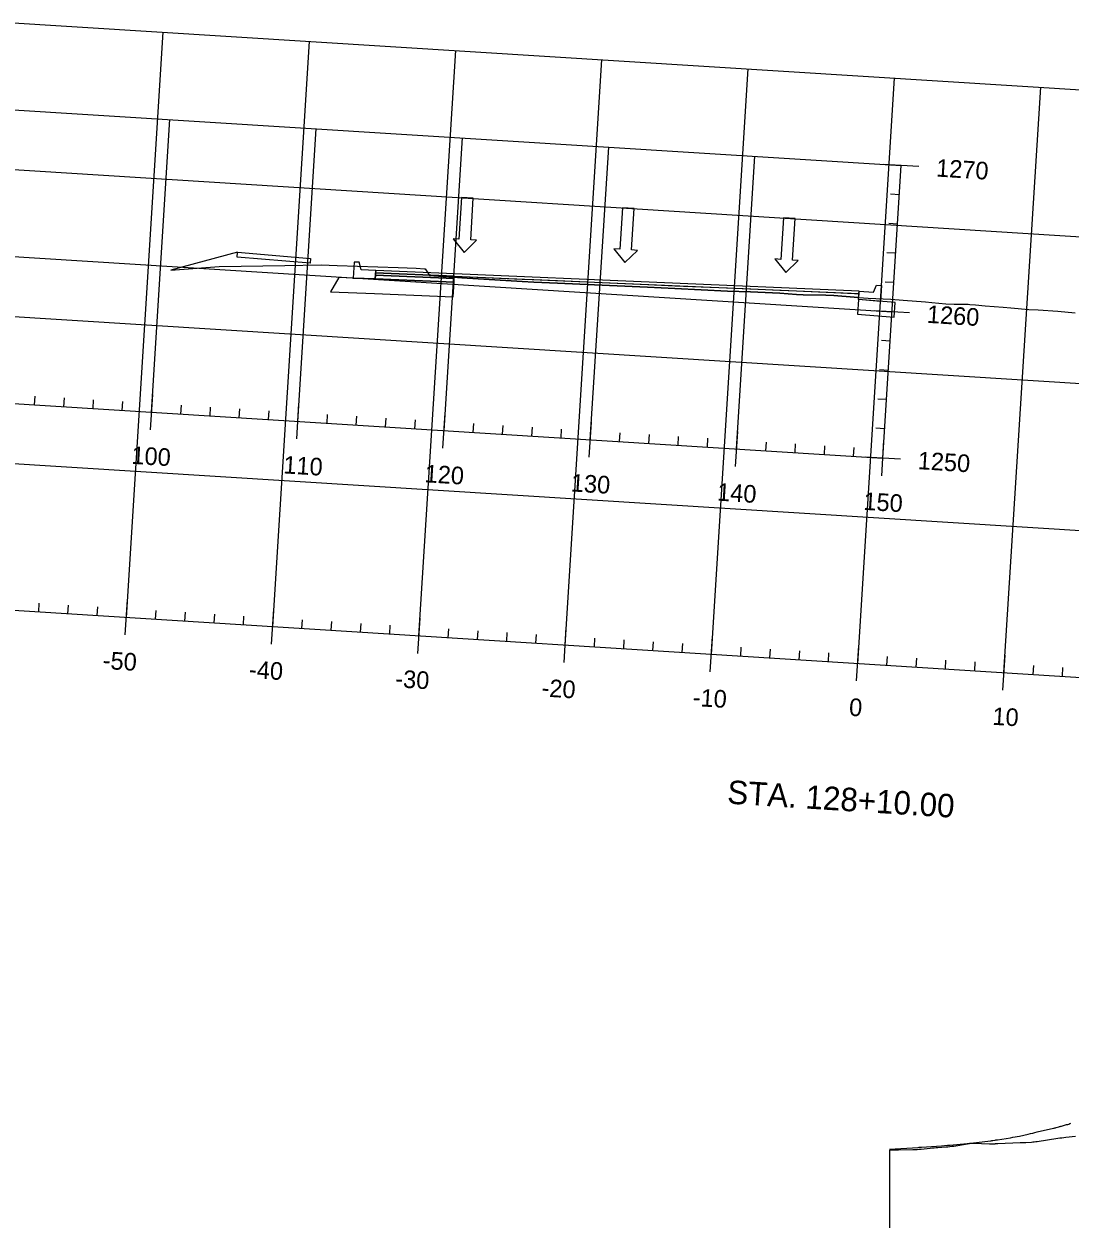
# Model space of a CAD drawing. Extents: x 658976 to 668726, y 639543 to 647196.
# Drawn here: x 660866.2 to 661223.2, y 641758.1 to 642165.7 of the extents above; entities that cross this region are included whole.
import ezdxf

# ---------------------------------------------------------------- set-up
doc = ezdxf.new("R2010")
doc.units = 0
for name, color, linetype in [('Ex_Major Contours', 7, 'Continuous'), ('R_Axis', 7, 'Continuous'), ('R_Axis Annot', 7, 'Continuous'), ('R_Exist Surface', 7, 'Continuous'), ('R_Fin Surface', 7, 'Continuous'), ('R_Grid', 7, 'Continuous'), ('R_MOT', 7, 'Continuous'), ('R_Proposed Const Limits', 7, 'Continuous'), ('R_Proposed Road', 7, 'Continuous'), ('R_Sub Surface', 7, 'Continuous')]:
    doc.layers.add(name, color=color, linetype=linetype)

msp = doc.modelspace()

# ---------------------------------------------------------------- linework, layer by layer
for points in [[(660986.27, 642081.64), (660981.27, 642081.86), (660980.6, 642084.4), (660978.93, 642084.51), (660978.59, 642079.05), (660986.09, 642078.73)], [(661151.15, 642074.59), (661156.14, 642074.18), (661157.12, 642076.62), (661158.79, 642076.52), (661158.45, 642071.06), (661150.97, 642071.68)]]:
    msp.add_lwpolyline(points, close=True)
at = {"layer": 'Ex_Major Contours'}
for points in [[(661161.51, 641781.89), (661171.34, 641782.56), (661171.64, 641782.58), (661172.15, 641782.61), (661172.24, 641782.62), (661172.32, 641782.62), (661172.41, 641782.63), (661172.49, 641782.63), (661179.31, 641783.12), (661180.31, 641783.19), (661181.3, 641783.27), (661182.29, 641783.36), (661183.28, 641783.45), (661189.25, 641784.04), (661189.27, 641784.04), (661189.31, 641784.04), (661196.04, 641784.82), (661196.24, 641784.84), (661196.44, 641784.87), (661196.64, 641784.89), (661196.83, 641784.92), (661197.62, 641785.04), (661197.82, 641785.07), (661198.01, 641785.1), (661198.21, 641785.13), (661198.41, 641785.16), (661202.85, 641785.85), (661203.61, 641785.98), (661204.37, 641786.11), (661205.13, 641786.26), (661205.88, 641786.43), (661208.9, 641787.11), (661209.65, 641787.28), (661210.41, 641787.45), (661211.16, 641787.63), (661211.91, 641787.8), (661217.45, 641789.09), (661217.68, 641789.14), (661217.91, 641789.2), (661218.14, 641789.26), (661218.36, 641789.32), (661219.27, 641789.57), (661219.5, 641789.63), (661219.72, 641789.7), (661219.95, 641789.76), (661220.18, 641789.82), (661221.98, 641790.31), (661222.36, 641790.41), (661222.73, 641790.52), (661223.1, 641790.64), (661223.47, 641790.76)], [(661161.68, 641753.1), (661161.68, 641781.57), (661161.68, 641781.58), (661161.69, 641781.59), (661161.69, 641781.6), (661161.7, 641781.61), (661161.75, 641781.64), (661161.77, 641781.64), (661161.78, 641781.65), (661161.79, 641781.65), (661161.81, 641781.65), (661163.46, 641781.66), (661163.74, 641781.66), (661164.02, 641781.67), (661164.3, 641781.67), (661164.58, 641781.68), (661169.48, 641781.79), (661170.21, 641781.82), (661170.94, 641781.86), (661171.66, 641781.91), (661172.39, 641781.98), (661175.39, 641782.29), (661176.06, 641782.35), (661176.74, 641782.42), (661177.42, 641782.47), (661178.09, 641782.52), (661180.8, 641782.7), (661181.48, 641782.75), (661182.15, 641782.83), (661182.83, 641782.91), (661183.5, 641783.02), (661188.82, 641783.93), (661188.93, 641783.94), (661189.05, 641783.96), (661189.16, 641783.96), (661189.27, 641783.97), (661189.73, 641783.97), (661189.85, 641783.97), (661189.96, 641783.97), (661190.08, 641783.97), (661190.19, 641783.96), (661195.68, 641783.72), (661195.77, 641783.71), (661195.86, 641783.71), (661195.95, 641783.71), (661196.04, 641783.71), (661196.41, 641783.72), (661196.5, 641783.72), (661196.59, 641783.73), (661196.68, 641783.73), (661196.78, 641783.74), (661197.61, 641783.81), (661197.68, 641783.82), (661197.76, 641783.83), (661197.84, 641783.83), (661197.92, 641783.84), (661198.23, 641783.87), (661198.31, 641783.88), (661198.38, 641783.89), (661198.46, 641783.89), (661198.54, 641783.89), (661206.14, 641784.19), (661206.62, 641784.21), (661207.11, 641784.23), (661207.59, 641784.25), (661208.07, 641784.27), (661210, 641784.37), (661210.48, 641784.4), (661210.96, 641784.44), (661211.44, 641784.5), (661211.91, 641784.56), (661218.93, 641785.66), (661219.62, 641785.76), (661220.32, 641785.86), (661221.01, 641785.95), (661221.71, 641786.04), (661225.05, 641786.43)]]:
    msp.add_lwpolyline(points, dxfattribs=at)
at = {"layer": 'R_Axis'}
for p, q in [((661159.27, 642017.62), (661165.54, 642117.43)), ((661171.52, 642117.05), (661159.55, 642117.8)), ((659662.22, 642111.64), (661159.27, 642017.62)), ((661164.91, 642107.45), (661161.91, 642107.63)), ((661164.28, 642097.47), (661161.29, 642097.65)), ((661163.66, 642087.49), (661160.66, 642087.67)), ((661163.03, 642077.51), (661160.03, 642077.69)), ((661168.39, 642067.15), (661156.41, 642067.9)), ((661161.77, 642057.54), (661158.78, 642057.73)), ((661161.15, 642047.56), (661158.15, 642047.75)), ((660869.84, 642035.8), (660870.03, 642038.79)), ((660909.38, 642027.3), (660910.14, 642039.28)), ((660879.82, 642035.17), (660880.01, 642038.17)), ((660889.8, 642034.55), (660889.99, 642037.54)), ((660899.78, 642033.92), (660899.97, 642036.91)), ((660919.74, 642032.67), (660919.93, 642035.66)), ((660929.72, 642032.04), (660929.91, 642035.03)), ((660959.28, 642024.17), (660960.04, 642036.15)), ((661160.52, 642037.58), (661157.53, 642037.77)), ((660939.7, 642031.41), (660939.89, 642034.41)), ((660949.68, 642030.79), (660949.87, 642033.78)), ((660969.64, 642029.53), (660969.83, 642032.53)), ((660979.62, 642028.91), (660979.81, 642031.9)), ((660989.6, 642028.28), (660989.79, 642031.27)), ((660999.58, 642027.65), (660999.77, 642030.65)), ((661009.19, 642021.04), (661009.94, 642033.01)), ((661019.54, 642026.4), (661019.73, 642029.39)), ((661029.52, 642025.77), (661029.71, 642028.77)), ((661039.5, 642025.14), (661039.69, 642028.14)), ((661049.48, 642024.52), (661049.67, 642027.51)), ((661059.09, 642017.9), (661059.84, 642029.88)), ((661108.99, 642014.77), (661109.74, 642026.75)), ((661159.89, 642027.6), (661156.9, 642027.79)), ((661069.44, 642023.26), (661069.63, 642026.26)), ((661079.42, 642022.64), (661079.61, 642025.63)), ((661089.4, 642022.01), (661089.59, 642025)), ((661099.39, 642021.38), (661099.57, 642024.38)), ((661119.35, 642020.13), (661119.53, 642023.12)), ((661129.33, 642019.5), (661129.51, 642022.5)), ((661158.89, 642011.63), (661159.64, 642023.61)), ((661139.31, 642018.88), (661139.49, 642021.87)), ((661149.29, 642018.25), (661149.48, 642021.24)), ((661165.26, 642017.25), (661153.28, 642018)), ((660402.17, 641994.63), (661899.22, 641900.61)), ((660871.24, 641965.17), (660871.43, 641968.16)), ((660881.22, 641964.54), (660881.41, 641967.53)), ((660891.2, 641963.91), (660891.39, 641966.91)), ((660900.81, 641957.3), (660901.56, 641969.28)), ((660911.16, 641962.66), (660911.35, 641965.65)), ((660950.71, 641954.16), (660951.46, 641966.14)), ((660921.15, 641962.03), (660921.33, 641965.03)), ((660931.13, 641961.41), (660931.31, 641964.4)), ((660941.11, 641960.78), (660941.29, 641963.77)), ((660961.07, 641959.53), (660961.25, 641962.52)), ((660971.05, 641958.9), (660971.23, 641961.89)), ((660981.03, 641958.27), (660981.22, 641961.27)), ((661000.61, 641951.03), (661001.36, 641963.01)), ((660991.01, 641957.65), (660991.2, 641960.64)), ((661010.97, 641956.39), (661011.16, 641959.39)), ((661020.95, 641955.77), (661021.14, 641958.76)), ((661030.93, 641955.14), (661031.12, 641958.13)), ((661040.91, 641954.51), (661041.1, 641957.51)), ((661050.51, 641947.9), (661051.27, 641959.87)), ((661060.87, 641953.26), (661061.06, 641956.25)), ((661070.85, 641952.63), (661071.04, 641955.63)), ((661080.83, 641952), (661081.02, 641955)), ((661090.81, 641951.38), (661091, 641954.37)), ((661100.41, 641944.76), (661101.17, 641956.74)), ((661110.77, 641950.12), (661110.96, 641953.12)), ((661150.32, 641941.63), (661151.07, 641953.61)), ((661120.75, 641949.5), (661120.94, 641952.49)), ((661130.73, 641948.87), (661130.92, 641951.86)), ((661140.71, 641948.24), (661140.9, 641951.24)), ((661160.67, 641946.99), (661160.86, 641949.98)), ((661170.65, 641946.36), (661170.84, 641949.36)), ((661200.22, 641938.49), (661200.97, 641950.47)), ((661180.63, 641945.74), (661180.82, 641948.73)), ((661190.61, 641945.11), (661190.8, 641948.1)), ((661210.57, 641943.86), (661210.76, 641946.85)), ((661220.56, 641943.23), (661220.74, 641946.22))]:
    msp.add_line(p, q, dxfattribs=at)
at = {"layer": 'R_Exist Surface'}
msp.add_lwpolyline([(660916.3, 642081.78), (660932.78, 642083.03), (660955.28, 642083.36), (660967.68, 642083.59), (660973.12, 642083.31), (660993.94, 642082.66), (661000.04, 642082.43), (661002.84, 642082.16), (661003.12, 642082.14), (661004.43, 642080.1), (661004.57, 642079.88), (661009.14, 642079.57), (661009.71, 642079.54), (661015.59, 642079.16), (661036.19, 642077.89), (661040.14, 642077.66), (661048.24, 642077.28), (661065.97, 642076.51), (661078.98, 642075.88), (661088.29, 642075.48), (661106.22, 642074.61), (661114.13, 642074.3), (661124.11, 642073.83), (661129.77, 642073.44), (661132.1, 642073.32), (661139.86, 642073.21), (661142.52, 642073.11), (661149.51, 642072.49), (661154.29, 642072.19), (661161.96, 642071.8), (661166.22, 642071.49), (661173.83, 642070.9), (661175.98, 642070.66), (661180.8, 642070.22), (661183.6, 642070.17), (661188.42, 642070.1), (661188.92, 642070.05), (661190.86, 642069.88), (661194.13, 642069.6), (661200.38, 642069.06), (661202.92, 642068.84), (661209.03, 642068.31), (661212.25, 642068.15), (661219.02, 642067.75), (661224.86, 642067.2)], dxfattribs=at)
at = {"layer": 'R_Fin Surface'}
for points in [[(661013.04, 642078.83), (660986.16, 642079.97), (660986.09, 642078.73), (661012.96, 642077.58)], [(661013.09, 642079.66), (660986.22, 642080.81), (660986.16, 642079.97), (661013.04, 642078.83)], [(661013.09, 642079.66), (661015.62, 642079.55), (661036.24, 642078.67), (661040.19, 642078.5), (661048.3, 642078.15), (661066.02, 642077.39), (661079.04, 642076.84), (661088.35, 642076.44), (661106.28, 642075.67), (661114.19, 642075.34), (661124.18, 642074.91), (661129.84, 642074.67), (661132.18, 642074.57), (661139.93, 642074.24), (661142.59, 642074.12), (661149.59, 642073.82), (661151.1, 642073.76), (661151.01, 642072.4), (661149.51, 642072.49), (661142.52, 642073.11), (661139.86, 642073.21), (661132.1, 642073.32), (661129.77, 642073.44), (661124.11, 642073.83), (661114.13, 642074.3), (661106.22, 642074.61), (661088.29, 642075.48), (661078.98, 642075.88), (661065.97, 642076.51), (661048.24, 642077.28), (661040.14, 642077.66), (661036.19, 642077.89), (661015.59, 642079.16), (661013.07, 642079.32)]]:
    msp.add_lwpolyline(points, close=True, dxfattribs=at)
at = {"layer": 'R_Grid'}
for p, q in [((659668.48, 642211.45), (661165.54, 642117.43)), ((660414.7, 642194.23), (661911.75, 642100.21)), ((659665.35, 642161.55), (661162.4, 642067.52)), ((660901.18, 641963.29), (660913.72, 642162.89)), ((660951.09, 641960.15), (660963.62, 642159.76)), ((661000.99, 641957.02), (661013.52, 642156.63)), ((661050.89, 641953.88), (661063.43, 642153.49)), ((661100.79, 641950.75), (661113.33, 642150.36)), ((661150.69, 641947.62), (661163.23, 642147.22)), ((660411.57, 642144.33), (661908.62, 642050.31)), ((661200.59, 641944.48), (661213.13, 642144.09)), ((660909.76, 642033.29), (660916.03, 642133.1)), ((660959.66, 642030.16), (660965.93, 642129.96)), ((661009.56, 642027.03), (661015.83, 642126.83)), ((661059.46, 642023.89), (661065.73, 642123.69)), ((661109.37, 642020.76), (661115.63, 642120.56)), ((661159.27, 642017.62), (661165.54, 642117.43)), ((659662.22, 642111.64), (661159.27, 642017.62)), ((660408.44, 642094.43), (661905.49, 642000.41)), ((660405.3, 642044.53), (661902.35, 641950.51)), ((660402.17, 641994.63), (661899.22, 641900.61))]:
    msp.add_line(p, q, dxfattribs=at)
at = {"layer": 'R_MOT'}
for p, q in [((661015.54, 642106.48), (661014.65, 642092.31)), ((661019.53, 642106.23), (661015.54, 642106.48)), ((661018.64, 642092.06), (661019.53, 642106.23)), ((661070.43, 642103.04), (661069.54, 642088.86)), ((661074.42, 642102.78), (661070.43, 642103.04)), ((661073.53, 642088.61), (661074.42, 642102.78)), ((661125.32, 642099.59), (661124.43, 642085.41)), ((661129.31, 642099.34), (661125.32, 642099.59)), ((661128.42, 642085.16), (661129.31, 642099.34)), ((661014.65, 642092.31), (661012.65, 642092.43)), ((661012.65, 642092.43), (661016.37, 642087.8)), ((661016.37, 642087.8), (661020.63, 642091.93)), ((661020.63, 642091.93), (661018.64, 642092.06)), ((661069.54, 642088.86), (661067.54, 642088.98)), ((661067.54, 642088.98), (661071.26, 642084.36)), ((661071.26, 642084.36), (661075.53, 642088.48)), ((661075.53, 642088.48), (661073.53, 642088.61)), ((661124.43, 642085.41), (661122.43, 642085.54)), ((661122.43, 642085.54), (661126.15, 642080.91)), ((661126.15, 642080.91), (661130.42, 642085.04)), ((661130.42, 642085.04), (661128.42, 642085.16))]:
    msp.add_line(p, q, dxfattribs=at)
at = {"layer": 'R_Proposed Const Limits'}
msp.add_lwpolyline([(660939.07, 642087.81), (660916.3, 642081.78)], dxfattribs=at)
msp.add_lwpolyline([(660986.27, 642081.64), (660986.22, 642080.81), (661013.09, 642079.66), (661151.1, 642073.76), (661151.15, 642074.59), (661013.14, 642080.49)], close=True, dxfattribs=at)
at = {"layer": 'R_Proposed Road'}
msp.add_lwpolyline([(660939.07, 642087.81), (660963.99, 642085.75), (660963.88, 642084.08), (660938.96, 642086.15)], close=True, dxfattribs=at)
at = {"layer": 'R_Sub Surface'}
for points in [[(661012.96, 642077.58), (660986.09, 642078.73), (660978.59, 642079.05), (660973.6, 642079.26), (660970.76, 642074.38), (660985.77, 642073.74), (661012.65, 642072.59)], [(661150.97, 642071.68), (661150.65, 642066.69), (661163.12, 642065.66), (661163.43, 642070.65)]]:
    msp.add_lwpolyline(points, close=True, dxfattribs=at)

# ---------------------------------------------------------------- texts
at = {"layer": 'R_Axis Annot'}
for s, height, p in [('1270', 6, (661177.32, 642113.68)), ('1260', 6, (661174.19, 642063.78)), ('100', 6, (660902.76, 642015.7)), ('110', 6, (660954.6, 642012.44)), ('1250', 6, (661171.06, 642013.88)), ('120', 6, (661002.8, 642009.41)), ('130', 6, (661052.7, 642006.28)), ('140', 6, (661102.6, 642003.15)), ('150', 6, (661152.51, 642000.01)), ('-50', 6, (660892.96, 641945.77)), ('-40', 6, (660942.86, 641942.63)), ('-30', 6, (660992.77, 641939.5)), ('-20', 6, (661042.67, 641936.37)), ('-10', 6, (661094.27, 641933.13)), ('0', 6, (661147.61, 641929.78)), ('10', 6, (661196.52, 641926.7)), ('STA. 128+10.00', 8, (661106.01, 641899.82))]:
    msp.add_text(s, height=height, rotation=356.4063, dxfattribs=at).set_placement(p)

doc.saveas('drawing.dxf')
